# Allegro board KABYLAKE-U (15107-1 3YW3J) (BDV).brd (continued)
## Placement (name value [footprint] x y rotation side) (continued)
PR176  -  [0R0805-PAD]  137.07 198.5 180 bottom
PR177  2D2R5J-1-GP  [R805H24]  46.39 197.61 90 bottom
PR178  7K5R3F-2-GP  [R603H22]  19.34 197.21 90 bottom
PR179  2D2R3-1-U-GP  [R603H22]  32.29 196.85 270 bottom
PR180  909R2F-GP  [R402H16]  32.55 195.2 180 bottom
PR181  51KR2F-L-GP  [R402H16]  28.61 195.2 180 bottom
PR182  100R2F-L1-GP-U  [R402H14]  24.67 195.2 0 bottom
PR183  10R2F-L-GP  [R402H14]  23.66 195.2 0 bottom
PR184  0R0402-PAD-2-GP  [0R0402-PAD-1]  22.64 195.2 0 bottom
PR185  49D9R2F-GP  [R402H16]  21.62 195.2 0 bottom
PR186  -  [0R0402-PAD]  20.61 195.2 180 bottom
PR187  118KR2F-1-GP  [R402H16]  25.69 194.31 180 bottom
PR188  -  [0R0402-PAD]  19.59 194.18 180 bottom
PR189  12K7R2F-GP  [R402H16]  32.42 192.91 90 bottom
PR190  10KR2F-2-GP  [R402H16]  19.59 192.28 0 bottom
PR191  -  [0R0805-PAD]  45.25 192.15 0 bottom
PR192  -  [0R0805-PAD]  43.21 192.15 0 bottom
PR193  -  [0R0805-PAD]  41.18 192.15 0 bottom
PR194  -  [0R0805-PAD]  39.15 192.15 0 bottom
PR195  -  [0R0805-PAD]  37.12 192.15 0 bottom
PR196  -  [0R0805-PAD]  35.09 192.15 0 bottom
PR197  1K24R2F-GP  [R402H16]  29.47 191.97 90 bottom
PR198  -  [0R0805-PAD]  24.16 171.58 180 bottom
PR199  -  [0R0805-PAD]  22.13 171.58 180 bottom
PR200  -  [0R0805-PAD]  20.1 171.58 180 bottom
PR201  -  [0R0805-PAD]  27.72 168.78 270 bottom
PR202  2D2R5J-1-GP  [R805H24]  26.91 154.23 0 bottom
PR203  2D2R5J-1-GP  [R805H24]  36.74 149.73 90 bottom
PR204  53K6R2F-GP  [R402H16]  22.74 145.11 270 bottom
PR206  51R2F-2-GP  [R402H16]  122.84 105.92 0 bottom
PR207  10KR2F-2-GP  [R402H16]  120.81 105.92 180 bottom
PR208  2D2R5J-1-GP  [R805H24]  128.79 104.9 180 bottom
PR209  100KR2F-L1-GP  [R402H16]  133.51 104.14 0 bottom
PR210  -  [0R0402-PAD]  132.49 104.14 180 bottom
PR211  100KR2F-L1-GP  [R402H16]  127.29 104.14 0 bottom
PR212  -  [0R0402-PAD]  126.27 104.14 180 bottom
PR213  0R0402-PAD-2-GP  [0R0402-PAD-1]  120.81 103.89 0 bottom
PR214  82KR2F-1-GP  [R402H16]  124.72 103.5 270 bottom
PR215  100R2F-L1-GP-U  [R402H14]  122.33 103.5 90 bottom
PR216  2D2R5J-1-GP  [R805H24]  134.02 102.23 90 bottom
PR217  100R2F-L1-GP-U  [R402H14]  121.7 102.23 270 bottom
PR218  0R0402-PAD-2-GP  [0R0402-PAD-1]  121.7 101.22 270 bottom
PR219  47KR2F-GP  [R402H16]  121.7 100.2 90 bottom
PR220  35K7R2F-GP  [R402H16]  133.38 99.44 270 bottom
PR221  10KR2J-3-GP  [R402H16]  57.69 100.84 270 bottom
PR222  10KR2J-3-GP  [R402H16]  73.95 97.79 90 bottom
PR223  0R0402-PAD-1-GP  [0R0402-PAD]  120.56 96.77 0 bottom
PR224  20KR2F-L-GP  [R402H16]  119.54 96.77 180 bottom
PR225  2D2R5J-1-GP  [R805H24]  134.02 96.65 270 bottom
PR226  18KR2F-GP  [R402H16]  122.08 96.27 90 bottom
PR227  10KR2J-3-GP  [R402H16]  73.57 96.01 0 bottom
PR228  2KR2F-3-GP  [R402H16]  122.08 95.25 270 bottom
PR229  -  [0R0402-PAD]  131.73 94.61 0 bottom
PR230  47KR2J-2-GP  [R402H16]  130.72 94.61 0 bottom
PR231  1KR2J-1-GP  [R402H16]  127.8 94.61 180 bottom
PR232  33KR2F-GP  [R402H16]  126.78 94.61 0 bottom
PR233  0R0402-PAD-2-GP  [0R0402-PAD-1]  124.62 94.61 180 bottom
PR234  20KR2F-L-GP  [R402H16]  122.08 94.23 90 bottom
PR235  10KR2J-3-GP  [R402H16]  57.69 99.82 270 bottom
PR236  -  [0R0402-PAD]  120.94 78.61 90 bottom
PR237  -  [0R0402-PAD]  120.94 77.6 90 bottom
PR238  -  [0R0402-PAD]  120.94 76.58 90 bottom
PR239  470KR2J-2-GP  [R402H16]  37.88 73.53 90 bottom
PR240  0R0402-PAD-1-GP  [0R0402-PAD]  121.95 73.03 90 bottom
PR241  10KR2F-2-GP  [R402H16]  28.48 69.85 180 bottom
PR242  100KR2F-L1-GP  [R402H16]  24.67 69.85 180 bottom
PR243  0R2J-2-GP  [R402H16]  25.69 62.99 0 bottom
PR244  0R2J-2-GP  [R402H16]  24.67 62.99 0 bottom
PR245  680KR2F-GP  [R402H16]  25.18 61.47 90 bottom
PR246  20R5F-1GP  [R805H24]  46.9 50.16 90 bottom
PR247  1D5R2F-GP  [R402H16]  40.8 48.84 90 bottom
PR248  100KR2J-1-GP  [R402H16]  35.47 48.77 90 bottom
PR249  120KR2F-L-GP  [R402H16]  35.47 47.75 270 bottom
PR250  10R2F-L-GP  [R402H14]  37.75 45.34 90 bottom
PR251  10KR2F-2-GP  [R402H16]  54.8 45.06 180 bottom
PR252  3D3MR2J-GP  [R402H16]  48.01 44.7 180 bottom
PR253  7D5R2F-GP  [R402H16]  37.75 44.32 90 bottom
PR254  10KR2F-2-GP  [R402H16]  37.75 43.31 90 bottom
PR255  102KR2F-GP  [R402H16]  43.98 40.77 180 bottom
PR256  -  [0R0402-PAD]  42.96 40.77 180 bottom
PR257  0R5J-5-GP  [R805H24]  66.2 38.61 0 bottom
PR258  0R5J-5-GP  [R805H24]  64.17 38.61 0 bottom
PR259  0R5J-5-GP  [R805H24]  62.14 38.61 0 bottom
PR260  0R5J-5-GP  [R805H24]  68.23 37.97 0 bottom
PR261  -  [0R0805-PAD]  148.12 28.19 180 bottom
PR262  -  [0R0805-PAD]  146.08 28.19 180 bottom
PR263  100KR2F-L1-GP  [R402H16]  154.49 25.98 90 bottom
PR264  -  [0R0805-PAD]  130.59 26.04 180 bottom
PR265  -  [0R0805-PAD]  128.56 26.04 180 bottom
PR266  33KR2F-GP  [R402H16]  149.89 34.04 270 bottom
PR267  10KR2J-3-GP  [R402H16]  149.89 33.02 270 bottom
PR268  2D2R5J-1-GP  [R805H24]  138.21 15.62 0 bottom
PR270  2D2R5J-1-GP  [R805H24]  35.21 161.16 270 bottom
PR271  10KR2J-3-GP  [R402H16]  147.35 33.02 90 bottom
PR272  33KR2F-GP  [R402H16]  147.35 34.04 90 bottom
PR273  2D2R5J-1-GP  [R805H24]  24.98 154.23 0 bottom
PT1  SE47U25VM-13-GP  [SE361414H241]  88.3 216.28 0 top
PT2  SE47U25VM-13-GP  [SE361414H241]  37.88 208.41 0 top
PT3  SE330U2D5VM-16-GP  [CT7343H83]  94.9 207.14 0 top
PT4  SE330U2D5VM-16-GP  [CT7343H83]  100.11 207.14 0 top
PT5  SE47U25VM-13-GP  [SE361414H241]  37.88 198.5 180 top
PT6  E560U6D3VM-3-GP  [ECAP-100D6D3H375]  67.34 197.1 0 top
PT7  E560U6D3VM-3-GP  [ECAP-100D6D3H375]  59.85 190.25 90 top
PT8  E560U6D3VM-3-GP  [ECAP-100D6D3H375]  52.74 186.56 0 top
PT9  SE47U25VM-13-GP  [SE361414H241]  23.15 179.07 180 top
PT10  E560U6D3VM-3-GP  [ECAP-100D6D3H375]  52.87 178.69 90 top
PT11  E560U6D3VM-3-GP  [ECAP-100D6D3H375]  49.94 165.99 0 top
PT12  E820U2D5VM-6-GP  [ECAP-100D6D3H375]  55.66 154.31 0 top
PT13  SE47U25VM-13-GP  [SE361414H241]  33.31 147.96 180 top
PT14  E820U2D5VM-6-GP  [ECAP-100D6D3H375]  54.64 146.43 0 top
PT15  E820U2D5VM-6-GP  [ECAP-100D6D3H375]  106.21 92.84 0 top
PT16  E820U2D5VM-6-GP  [ECAP-100D6D3H375]  106.21 84.96 0 top
PT17  SE47U25VM-13-GP  [SE361414H241]  136.43 83.06 180 top
PT18  SE47U25VM-13-GP  [SE361414H241]  132.37 24.64 90 top
PT19  SE47U25VM-13-GP  [SE361414H241]  142.78 24.64 270 top
PT20  SE220U6D3VM-3GP  [SE3116H241]  135.03 7.87 90 top
PT21  SE220U6D3VM-3GP  [SE3116H241]  145.07 7.87 90 top
PU1  AON6520-GP  [PPAK-8P-5262H40]  44.99 215.26 90 top
PU2  AON6510-GP  [PPAK-8P-5262H40]  46.77 208.66 270 top
PU3  AON6510-GP  [PPAK-8P-5262H40]  46.77 202.06 270 top
PU4  AON6520-GP  [PPAK-8P-5262H40]  44.99 195.45 90 top
PU5  AON6510-GP  [PPAK-8P-5262H40]  32.16 182.5 270 top
PU6  AON6520-GP  [PPAK-8P-5262H40]  30.39 175.9 90 top
PU7  AON7410-GP  [PPAK-8P-3232H36]  33.43 166.12 90 top
PU8  NCP81253MNTBG-1-GP  [LFDFN8G2-G1309H40]  26.7 162.18 90 top
PU9  AON7506-GP  [PPAK-8P-3232H36]  34.96 161.67 270 top
PU10  APL5930KAI-TRG-1-GP  [SOIC8-G3530H63]  91.47 124.21 90 top
PU11  APL5912-KAC-TRG-GP  [SOIC8-G3530H63]  112.68 103.5 270 top
PU12  AON6510-GP  [PPAK-8P-5262H40]  127.68 89.03 90 top
PU13  AON6520-GP  [PPAK-8P-5262H40]  129.43 80.26 270 top
PU14  APW8713QBI-TRG-1-GP  [QFN23G4-G2P-1H42]  117.13 75.18 270 top
PU15  AO4407AL-GP  [SOIC8H69]  40.8 71.37 180 top
PU16  AO4407AL-GP  [SOIC8H69]  64.93 37.47 180 top
PU17  RT6575DGQW-GP  [QFN20-G1D75H32]  152.69 22.23 270 top
PU18  AON6520-GP  [PPAK-8P-5262H40]  93 222.5 180 bottom
PU19  AON6510-GP  [PPAK-8P-5262H40]  101.76 220.6 0 bottom
PU20  RT8231AGQW-GP  [QFN20-G1D75H32]  85.25 211.58 0 bottom
PU21  APL5930KAI-TRG-1-GP  [SOIC8-G3530H63]  134.02 204.98 270 bottom
PU22  AON6510-GP  [PPAK-8P-5262H40]  46.77 208.66 90 bottom
PU23  AON6510-GP  [PPAK-8P-5262H40]  46.77 202.06 90 bottom
PU24  NCP81206MNTXG-1-GP  [LFQFN52J6-G4D8-1H40]  25.94 201.55 180 bottom
PU25  AON6510-GP  [PPAK-8P-5262H40]  32.16 182.5 90 bottom
PU26  AON6520-GP  [PPAK-8P-5262H40]  30.39 175.9 270 bottom
PU27  AON6510-GP  [PPAK-8P-5262H40]  36.48 154.05 90 bottom
PU28  RT8237CZQW-2-GP  [DFN10G3-G265175H32]  23.66 149.1 270 bottom
PU29  AON6520-GP  [PPAK-8P-5262H40]  34.7 145.41 270 bottom
PU30  AON6510-GP  [PPAK-8P-5262H40]  127.68 89.03 270 bottom
PU31  AON6520-GP  [PPAK-8P-5262H40]  129.43 80.26 90 bottom
PU32  SIS412DN-T1-GE3-GP  [PPAK-8P-2H45]  43.21 54.99 0 bottom
PU33  SIS412DN-T1-GE3-GP  [PPAK-8P-2H45]  38.77 56.52 180 bottom
PU34  BQ24727RGRR-1-GP  [QFN20G3D5-G2D15H40]  42.32 45.21 90 bottom
PU35  AON7410-GP  [PPAK-8P-3232H36]  145.58 20.83 180 bottom
PU36  AON7410-GP  [PPAK-8P-3232H36]  131.1 20.83 180 bottom
PU37  AON7506-GP  [PPAK-8P-3232H36]  141.13 19.3 0 bottom
PU38  AON7506-GP  [PPAK-8P-3232H36]  135.54 19.3 0 bottom
PWRCN1  ACES-CON10-30-GP  [51530-01041-W01]  26.75 22.5 270 top
Q1  MMBT3904DW-GP  [SOT-363H44]  77.88 224.41 270 top
Q2  2N7002K-2-GP  [SOT23DGS2D4H44]  146.21 223.9 90 top
Q3  MMBT3904DW-GP  [SOT-363H44]  82.33 219.33 270 top
Q4  2N7002A-7-GP  [SOT23DGS2D4H48]  16.47 186.69 90 top
Q5  MMBT3904DW-GP  [SOT-363H44]  16.67 183.39 270 top
Q6  MMBT3904-4-GP  [SOT23CBE2D4H44]  161.96 182.63 90 top
Q7  2N7002A-7-GP  [SOT23DGS2D4H48]  16.67 179.96 90 top
Q8  MMBT3904DW-GP  [SOT-363H44]  16.67 176.53 270 top
Q9  2N7002KDW-1-GP  [SOT-363H44]  158.91 174.62 90 top
Q10  MMBT3904DW-GP  [SOT-363H44]  163.36 174.37 180 top
Q11  2N7002A-7-GP  [SOT23DGS2D4H48]  162.97 168.66 180 top
Q12  MMBT3904DW-GP  [SOT-363H44]  15.53 159.13 0 top
Q13  MMBT3904DW-GP  [SOT-363H44]  22.64 143.38 90 top
Q14  2N7002A-7-GP  [SOT23DGS2D4H48]  35.09 140.21 0 top
Q16  2N7002A-7-GP  [SOT23DGS2D4H48]  47.02 120.78 90 top
Q17  DMN5L06K-7-GP  [SOT23DGS2D4H48]  153.07 118.49 90 top
Q18  DMN5L06K-7-GP  [SOT23DGS2D4H48]  156.75 118.36 0 top
Q21  2N7002EDW-2-GP  [SOT-363H44]  76.23 116.2 270 top
Q22  MMBT3904-4-GP  [SOT23CBE2D4H44]  143.04 115.7 0 top
Q23  2N7002A-7-GP  [SOT23DGS2D4H48]  146.59 115.7 0 top
Q24  LMBT3904LT1G-GP  [SOT23CBE2D4H44]  168.31 111.63 90 top
Q25  2N7002-11-GP  [SOT23DGS2D4H44]  168.56 87.25 270 top
Q26  AZ5125-02S-R7G-GP  [SOT23-2D4-312H46]  174.02 85.47 0 top
Q27  AZ5125-02S-R7G-GP  [SOT23-2D4-312H46]  177.96 85.47 0 top
Q28  2N7002K-2-GP  [SOT23DGS2D4H44]  100.36 84.33 270 top
Q29  2N7002K-2-GP  [SOT23DGS2D4H44]  147.86 81.03 270 top
Q30  MMBT3904-4-GP  [SOT23CBE2D4H44]  151.67 79.76 0 top
Q31  2N7002A-7-GP  [SOT23DGS2D4H48]  55.41 79.5 90 top
Q32  AO3418L-GP  [SOT23DGS2D8H50]  64.04 78.74 180 top
Q33  MMBT3904DW-GP  [SOT-363H44]  54.26 75.56 90 top
Q34  2N7002KDW-GP  [SOT-363H44]  74.33 73.41 90 top
Q35  AO3413L-GP  [SOT23DGS2D8H50]  80.68 72.52 0 top
Q36  2N7002KDW-GP  [SOT-363H44]  147.23 67.56 270 top
Q37  2N7002A-7-GP  [SOT23DGS2D4H48]  82.33 66.67 180 top
Q38  2N7002A-7-GP  [SOT23DGS2D4H48]  164.12 65.28 270 top
Q39  2N7002KDW-GP  [SOT-363H44]  75.98 57.4 270 top
Q40  2N7002K-2-GP  [SOT23DGS2D4H44]  107.48 47.88 180 top
Q41  DMP2130L-7-GP  [SOT23DGS2D4H48]  145.07 44.96 0 top
Q42  AZ5125-02S-R7G-GP  [SOT23-2D4-312H46]  84.11 41.66 270 top
Q43  2N7002A-7-GP  [SOT23DGS2D4H48]  142.27 30.23 90 top
Q44  2N7002A-7-GP  [SOT23DGS2D4H48]  35.21 21.97 90 top
Q45  MMBT3904DW-GP  [SOT-363H44]  32.55 7.87 90 top
Q46  MMBT3904-4-GP  [SOT23CBE2D4H44]  42.96 6.99 0 top
Q47  MMBT3904-4-GP  [SOT23CBE2D4H44]  47.53 6.99 0 top
Q48  2N7002A-7-GP  [SOT23DGS2D4H48]  153.83 209.17 270 bottom
Q49  MMBT3904-4-GP  [SOT23CBE2D4H44]  150.02 209.17 90 bottom
Q50  AO3413L-GP  [SOT23DGS2D8H50]  146.46 201.68 0 bottom
Q51  2N7002A-7-GP  [SOT23DGS2D4H48]  56.8 122.17 90 bottom
Q52  MMBT3906-4-GP  [SOT23CBE2D4H44]  112.81 122.05 180 bottom
Q53  2N7002EDW-2-GP  [SOT-363H44]  76.23 116.2 270 bottom
Q54  2N7002A-7-GP  [SOT23DGS2D4H48]  92.74 110.49 180 bottom
Q55  AO3413L-GP  [SOT23DGS2D8H50]  41.69 100.08 0 bottom
Q56  2N7002A-7-GP  [SOT23DGS2D4H48]  38.01 99.95 180 bottom
Q57  2N7002A-7-GP  [SOT23DGS2D4H48]  157.01 78.11 270 bottom
Q58  MMBT3904DW-GP  [SOT-363H44]  54.26 75.56 90 bottom
Q59  MMBT3906-4-GP  [SOT23CBE2D4H44]  138.21 68.83 180 bottom
Q60  2N7002KDW-GP  [SOT-363H44]  85.76 64.9 270 bottom
Q61  AO3418L-GP  [SOT23DGS2D8H50]  61.25 62.23 180 bottom
Q62  LMBT3906LT1G-1-GP  [SOT23CBE2D4H44]  64.93 61.98 270 bottom
Q63  2N7002K-2-GP  [SOT23DGS2D4H44]  25.94 59.05 180 bottom
Q65  2N7002KDW-GP  [SOT-363H44]  75.98 57.4 270 bottom
Q66  2N7002A-7-GP  [SOT23DGS2D4H48]  160.56 51.56 270 bottom
Q67  2N7002K-2-GP  [SOT23DGS2D4H44]  145.32 48.77 180 bottom
Q68  2N7002A-7-GP  [SOT23DGS2D4H48]  163.99 45.72 90 bottom
Q69  2N7002A-7-GP  [SOT23DGS2D4H48]  141.77 44.83 0 bottom
Q70  2N7002A-7-GP  [SOT23DGS2D4H48]  145.32 43.56 0 bottom
Q71  MMBT3904DW-GP  [SOT-363H44]  155.86 41.91 90 bottom
Q72  2N7002KDW-GP  [SOT-363H44]  163.99 41.4 270 bottom
Q73  MMBT3904-4-GP  [SOT23CBE2D4H44]  50.45 36.45 180 bottom
Q74  2N7002A-7-GP  [SOT23DGS2D4H48]  55.02 36.32 0 bottom
Q75  AO4286-GP  [SOIC8H69]  39.28 35.31 270 bottom
Q76  MMBT3904-4-GP  [SOT23CBE2D4H44]  42.71 28.32 270 bottom
Q77  MMBT3904-4-GP  [SOT23CBE2D4H44]  25.94 27.18 0 bottom
Q78  MMBT3904DW-GP  [SOT-363H44]  24.8 21.84 0 bottom
Q79  2N7002A-7-GP  [SOT23DGS2D4H48]  25.18 12.83 180 bottom
Q80  MMBT3904-4-GP  [SOT23CBE2D4H44]  46.52 6.99 0 bottom
Q81  AO3413L-GP  [SOT23DGS2D8H50]  41.94 6.86 180 bottom
Q82  2N7002K-2-GP  [SOT23DGS2D4H44]  46.26 19.68 0 top
Q83  2N7002A-7-GP  [SOT23DGS2D4H48]  112.68 102.62 90 bottom
Q84  2N7002A-7-GP  [SOT23DGS2D4H48]  154.59 47.75 180 bottom
R1  51R2J-2-GP  [R402H16]  15.53 224.66 0 top
R2  1KR2J-1-GP  [R402H16]  16.67 224.66 0 top
R3  1KR2J-1-GP  [R402H16]  17.81 224.66 0 top
R4  -  [0R0402-PAD]  18.83 224.66 180 top
R5  1K5R2J-3-GP  [R402H16]  47.84 224.54 270 top
R6  10KR2J-3-GP  [R402H16]  143.54 224.54 180 top
R7  -  [0R0402-PAD]  28.99 224.16 180 top
R8  -  [0R0402-PAD]  30.01 224.16 180 top
R9  1KR2J-1-GP  [R402H16]  32.93 224.16 0 top
R10  -  [0R0402-PAD]  33.94 224.16 0 top
R11  -  [0R0402-PAD]  34.96 224.16 0 top
R12  -  [0R0402-PAD]  35.97 224.16 180 top
R13  51R2J-2-GP  [R402H16]  36.99 224.16 180 top
R14  -  [0R0402-PAD]  38.01 224.16 0 top
R15  -  [0R0402-PAD]  39.02 224.16 0 top
R16  0R2J-2-GP  [R402H16]  40.04 224.16 180 top
R17  100KR2J-1-GP  [R402H16]  41.05 224.16 0 top
R18  -  [0R0402-PAD]  42.07 224.16 0 top
R19  150R2J-L1-GP-U  [R402H16]  43.21 224.16 0 top
R20  1KR2J-1-GP  [R402H16]  44.36 224.16 0 top
R21  0R2J-2-GP  [R402H16]  49.56 224.16 180 top
R22  -  [0R0402-PAD]  50.58 224.16 0 top
R23  -  [0R0402-PAD]  46.39 224.03 180 top
R24  10KR2J-3-GP  [R402H16]  122.08 223.77 180 top
R25  100KR2J-1-GP  [R402H16]  123.1 223.77 180 top
R26  0R2J-2-GP  [R402H16]  52.36 223.65 90 top
R27  0R2J-2-GP  [R402H16]  47.84 223.52 270 top
R28  -  [0R0402-PAD]  52.36 222.63 270 top
R29  10KR2J-3-GP  [R402H16]  79.41 222.38 90 top
R30  0R0402-PAD-2-GP  [0R0402-PAD-1]  123.99 222 90 top
R31  -  [0R0402-PAD]  105.82 221.87 180 top
R32  -  [0R0402-PAD]  52.36 221.49 90 top
R33  2K2R2J-2-GP  [R402H16]  12.23 220.98 0 top
R34  0R0402-PAD-2-GP  [0R0402-PAD-1]  123.99 220.98 270 top
R35  -  [0R0402-PAD]  52.36 220.34 90 top
R36  0R2J-2-GP  [R402H16]  125.89 220.34 270 top
R37  0R2J-2-GP  [R402H16]  104.58 219.84 180 top
R38  10KR2J-3-GP  [R402H16]  75.09 219.71 180 top
R39  0R2J-2-GP  [R402H16]  123.99 219.71 270 top
R40  100R2F-L1-GP-U  [R402H14]  11.84 219.46 90 top
R41  0R2J-2-GP  [R402H16]  125.89 219.07 270 top
R42  10KR2J-3-GP  [R402H16]  79.15 218.82 180 top
R43  -  [0R0402-PAD]  106.84 218.44 90 top
R44  0R2J-2-GP  [R402H16]  123.99 218.44 270 top
R45  0R2J-2-GP  [R402H16]  125.89 217.81 270 top
R46  0R0402-PAD-2-GP  [0R0402-PAD-1]  106.46 217.42 270 top
R47  0R2J-2-GP  [R402H16]  79.54 217.3 90 top
R48  0R2J-2-GP  [R402H16]  81.44 215.77 270 top
R49  0R2J-2-GP  [R402H16]  123.99 217.42 270 top
R50  0R0402-PAD-2-GP  [0R0402-PAD-1]  106.46 216.41 270 top
R51  0R2J-2-GP  [R402H16]  79.54 216.28 90 top
R52  0R2J-2-GP  [R402H16]  123.99 216.41 270 top
R53  0R0402-PAD-2-GP  [0R0402-PAD-1]  106.46 214.76 270 top
R54  0R0402-PAD-2-GP  [0R0402-PAD-1]  106.46 213.74 270 top
R55  0R0402-PAD-2-GP  [0R0402-PAD-1]  105.57 208.2 0 top
R56  0R0402-PAD-2-GP  [0R0402-PAD-1]  106.59 208.2 0 top
R57  4K7R2J-2-GP  [R402H16]  17.18 211.46 0 top
R58  1KR2J-1-GP  [R402H16]  19.16 210.69 270 top
R59  8K2R2F-1-GP  [R402H16]  17.18 209.55 180 top
R60  0R0402-PAD-2-GP  [0R0402-PAD-1]  18.7 209.17 0 top
R61  20KR2J-L2-GP  [R402H16]  17.18 207.65 180 top
R62  -  [0R0402-PAD]  163.99 206.5 0 top
R63  -  [0R0402-PAD]  113.95 201.04 90 top
R64  0R2J-2-GP  [R402H16]  116.14 200.38 90 top
R65  1KR2J-1-GP  [R402H16]  70.26 192.15 90 top
R66  -  [0R0402-PAD]  100.87 192.02 0 top
R67  -  [0R0805-PAD]  15.65 191.39 180 top
R68  -  [0R0805-PAD]  17.69 191.39 180 top
R69  100R2F-L1-GP-U  [R402H14]  76.87 190.5 0 top
R70  60D4R2F-GP  [R402H16]  69.5 189.87 0 top
R71  10KR2J-3-GP  [R402H16]  71.79 189.87 180 top
R72  1KR2J-1-GP  [R402H16]  70.77 189.1 180 top
R73  1KR2J-1-GP  [R402H16]  72.8 189.1 180 top
R74  1KR2J-1-GP  [R402H16]  73.82 189.1 180 top
R75  100R2F-L1-GP-U  [R402H14]  77.76 188.98 90 top
R76  1KR2J-1-GP  [R402H16]  19.85 188.8 90 top
R77  10KR2J-3-GP  [R402H16]  22 188.09 90 top
R78  10KR2J-3-GP  [R402H16]  23.66 188.09 0 top
R79  0R3J-0-U-GP  [R603H22]  160.18 188.09 90 top
R80  -  [0R0402-PAD]  19.85 187.78 270 top
R81  1KR2J-1-GP  [R402H16]  67.39 187.58 180 top
R82  499R2F-2-GP  [R402H16]  68.41 187.58 0 top
R83  100KR2J-1-GP  [R402H16]  64.68 187.32 180 top
R84  0R3J-0-U-GP  [R603H22]  164.5 186.94 180 top
R85  10KR2J-3-GP  [R402H16]  20.48 186.18 270 top
R86  54D9R2F-L1-GP  [R402H16]  64.68 185.42 0 top
R87  100R2F-L1-GP-U  [R402H14]  67.42 184.66 0 top
R88  0R0402-PAD-2-GP  [0R0402-PAD-1]  68.44 184.66 180 top
R89  0R0402-PAD-2-GP  [0R0402-PAD-1]  65.69 184.53 0 top
R90  10KR2J-3-GP  [R402H16]  12.35 184.15 0 top
R91  10KR2J-3-GP  [R402H16]  13.37 184.15 0 top
R92  56R2J-4-GP  [R402H16]  67.42 182.63 180 top
R93  220R2J-L2-GP  [R402H16]  68.44 182.63 180 top
R94  1KR2J-1-GP  [R402H16]  65.36 181.64 0 top
R95  10KR2J-3-GP  [R402H16]  12.35 181.23 180 top
R96  -  [0R0402-PAD]  67.98 181.1 90 top
R97  10KR2J-3-GP  [R402H16]  161.04 186.23 180 top
R98  1KR2J-1-GP  [R402H16]  158.66 180.59 90 top
R99  51R2J-2-GP  [R402H16]  67.98 179.96 270 top
R100  51R2J-2-GP  [R402H16]  65.69 179.71 180 top
R101  -  [0R0402-PAD]  158.66 179.45 270 top
R102  1KR2J-1-GP  [R402H16]  13.5 179.2 0 top
R103  51R2J-2-GP  [R402H16]  67.85 178.56 270 top
R104  10KR2J-3-GP  [R402H16]  158.66 178.44 90 top
R105  51R2J-2-GP  [R402H16]  65.69 177.8 180 top
R106  10KR2J-3-GP  [R402H16]  161.2 177.24 270 top
R107  1KR2J-1-GP  [R402H16]  67.85 176.91 270 top
R108  10KR2J-3-GP  [R402H16]  12.45 176.68 0 top
R109  10KR2J-3-GP  [R402H16]  161.32 175.13 180 top
R110  51R2J-2-GP  [R402H16]  66.33 175.77 270 top
R111  51R2J-2-GP  [R402H16]  66.33 174.5 270 top
R112  NTC-100K-8-GP  [NTC-603H38]  40.17 174.12 90 top
R113  51R2J-2-GP  [R402H16]  63.53 173.99 180 top
R114  51R2J-2-GP  [R402H16]  64.68 173.99 180 top
R115  -  [0R0402-PAD]  64.17 171.96 270 top
R116  10KR2J-3-GP  [R402H16]  165.84 171.96 90 top
R117  10R6J-1-GP  [R1206H28]  159.42 171.7 90 top
R118  10KR2J-3-GP  [R402H16]  159.8 169.93 270 top
R119  NTC-100K-8-GP  [NTC-603H38]  102.9 169.67 180 top
R120  10KR2J-3-GP  [R402H16]  159.42 168.15 180 top
R121  10KR2J-3-GP  [R402H16]  165.39 167.77 180 top
R122  150KR2J-GP  [R402H16]  102.52 163.96 270 top
R123  33R2J-2-GP  [R402H16]  102.52 162.94 270 top
R124  33R2J-2-GP  [R402H16]  102.52 161.93 270 top
R125  -  [0R0402-PAD]  15.02 161.54 270 top
R126  33R2J-2-GP  [R402H16]  102.52 160.91 270 top
R127  33R2J-2-GP  [R402H16]  102.52 159.89 270 top
R128  1MR2J-1-GP  [R402H16]  65.82 159.84 90 top
R129  10KR2F-2-GP  [R402H16]  18.07 159.38 90 top
R130  0R2J-2-GP  [R402H16]  102.52 158.5 270 top
R131  10KR2F-2-GP  [R402H16]  18.07 158.37 90 top
R132  1K8R2F-GP  [R402H16]  15.15 156.21 270 top
R133  5K6R2F-2-GP  [R402H16]  15.15 155.19 90 top
R134  33R2J-2-GP  [R402H16]  102.06 154.25 90 top
R135  1KR2J-1-GP  [R402H16]  102.52 152.53 270 top
R136  -  [0R0402-PAD]  100.36 152.15 90 top
R137  0R0603-PAD-2-GP-U  [0R0603-PAD-1-U]  102.9 150.62 180 top
R138  -  [0R0402-PAD]  59.6 147.19 90 top
R139  -  [0R0402-PAD]  59.6 146.18 90 top
R140  -  [0R0402-PAD]  59.6 145.16 90 top
R141  -  [0R0402-PAD]  59.6 144.15 90 top
R142  -  [0R0402-PAD]  59.6 143.13 90 top
R144  -  [0R0402-PAD]  59.6 142.11 90 top
R146  -  [0R0402-PAD]  52.87 141.73 0 top
R147  10KR2J-3-GP  [R402H16]  68.11 141.73 0 top
R148  -  [0R0402-PAD]  42.07 141.48 0 top
R149  -  [0R0402-PAD]  44.23 141.48 0 top
R150  -  [0R0402-PAD]  46.26 141.48 0 top
R151  3KR2J-2-GP  [R402H16]  70.01 141.43 270 top
R152  10KR2J-3-GP  [R402H16]  75.85 141.48 270 top
R153  -  [0R0402-PAD]  102.9 140.08 180 top
R156  -  [0R0805-PAD]  54.39 140.72 0 top
R157  10KR2J-3-GP  [R402H16]  21.24 140.59 0 top
R158  10KR2J-3-GP  [R402H16]  22.28 140.59 180 top
R159  10KR2J-3-GP  [R402H16]  23.3 140.59 180 top
R160  1KR2J-1-GP  [R402H16]  88.43 140.59 90 top
R161  -  [0R0402-PAD]  70.01 140.41 90 top
R162  49K9R2F-L-GP  [R402H16]  86.01 139.95 90 top
R163  -  [0R0402-PAD]  66.33 135.25 270 top
R164  49K9R2F-L-GP  [R402H16]  86.01 138.94 90 top
R165  10KR2J-3-GP  [R402H16]  71.92 138.43 90 top
R166  10KR2J-3-GP  [R402H16]  100.36 138.68 0 top
R167  10KR2J-3-GP  [R402H16]  74.71 138.76 270 top
R168  200R2F-L-GP  [R402H16]  86.01 137.79 270 top
R169  -  [0R0402-PAD]  50.83 137.92 180 top
R170  -  [0R0402-PAD]  51.85 137.92 180 top
R171  10KR2J-3-GP  [R402H16]  34.7 137.79 90 top
R172  10KR2J-3-GP  [R402H16]  72.3 137.29 90 top
R173  1KR2J-1-GP  [R402H16]  86.01 136.78 90 top
R174  22R2J-2-GP  [R402H16]  103.03 136.78 180 top
R175  -  [0R0402-PAD]  78.52 136.65 180 top
R176  15R2J-GP  [R402H16]  85.25 135.76 90 top
R177  0R2J-2-GP  [R402H16]  81.57 135.25 180 top
R178  -  [0R0402-PAD]  82.58 135.25 180 top
R179  -  [0R0402-PAD]  83.6 135.25 0 top
R180  -  [0R0402-PAD]  76.87 135.13 90 top
R181  -  [0R0402-PAD]  78.77 135.13 90 top
R182  -  [0R0402-PAD]  84.74 134.24 0 top
R183  15R2J-GP  [R402H16]  85.76 134.24 180 top
R184  -  [0R0402-PAD]  78.77 134.11 90 top
R185  1KR2J-1-GP  [R402H16]  87.28 133.86 270 top
R186  22R2J-2-GP  [R402H16]  103.03 133.6 180 top
R187  10KR2J-3-GP  [R402H16]  64.52 132.46 0 top
R188  10KR2J-3-GP  [R402H16]  65.54 131.88 180 top
R189  10KR2J-3-GP  [R402H16]  66.56 131.88 180 top
R190  10KR2J-3-GP  [R402H16]  67.6 133.48 0 top
R191  10KR2J-3-GP  [R402H16]  68.61 133.48 0 top
R192  10KR2J-3-GP  [R402H16]  70.26 133.48 180 top
R193  -  [0R0402-PAD]  100.62 132.08 180 top
R194  15R2J-GP  [R402H16]  85.25 131.95 180 top
R195  1KR2J-1-GP  [R402H16]  86.27 131.95 180 top
R196  15R2J-GP  [R402H16]  87.28 131.95 180 top
R197  15R2J-GP  [R402H16]  88.3 131.95 180 top
R198  10MR2J-L-GP  [R402H16]  89.57 131.95 180 top
R199  1KR2J-1-GP  [R402H16]  83.73 131.32 90 top
R200  1KR2J-1-GP  [R402H16]  83.73 130.3 90 top
R201  -  [0R0402-PAD]  77.38 129.67 270 top
R202  0R2J-2-GP  [R402H16]  101.63 129.54 180 top
R203  -  [0R0402-PAD]  96.27 128.73 0 top
R204  -  [0R0402-PAD]  97.29 128.73 0 top
R205  -  [0R0402-PAD]  77.38 128.65 270 top
R206  10KR2J-3-GP  [R402H16]  100.62 128.65 180 top
R207  -  [0R0402-PAD]  93.23 128.55 180 top
R208  0R2J-2-GP  [R402H16]  94.24 128.55 180 top
R209  0R2J-2-GP  [R402H16]  95.26 128.55 180 top
R210  -  [0R0402-PAD]  91.6 128.52 180 top
R213  1KR2J-1-GP  [R402H16]  100.62 126.24 0 top
R214  0R2J-2-GP  [R402H16]  161.45 125.86 270 top
R215  -  [0R0402-PAD]  159.55 124.84 90 top
R216  10KR2J-3-GP  [R402H16]  108.49 124.08 0 top
R217  0R0402-PAD-2-GP  [0R0402-PAD-1]  109.51 124.08 180 top
R220  -  [0R0402-PAD]  86.65 122.05 90 top
R223  10KR2J-3-GP  [R402H16]  44.61 120.78 180 top
R224  1KR2J-1-GP  [R402H16]  152.94 120.78 270 top
R225  1KR2J-1-GP  [R402H16]  155.99 120.78 90 top
R226  10KR2J-3-GP  [R402H16]  106.46 120.65 270 top
R228  1KR2J-1-GP  [R402H16]  159.04 118.87 180 top
R229  10KR2J-3-GP  [R402H16]  160.69 118.87 180 top
R230  0R3J-0-U-GP  [R603H22]  115.6 118.36 0 top
R231  15KR2F-GP  [R402H16]  162.21 118.36 90 top
R233  8K2R2J-3-GP  [R402H16]  150.15 117.47 90 top
R235  10KR2J-3-GP  [R402H16]  73.19 116.97 90 top
R237  10KR3J-L1-GP  [R603H22]  79.36 116.46 270 top
R238  10KR3J-L1-GP  [R603H22]  73.06 115.82 90 top
R240  10KR2J-3-GP  [R402H16]  93.25 114.55 0 top
R241  10KR2J-3-GP  [R402H16]  81.69 114.05 270 top
R242  10KR2J-3-GP  [R402H16]  94.27 114.55 0 top
R243  2K49R2F-GP  [R402H16]  72.91 114.6 270 top
R244  200R2F-L-GP  [R402H16]  77.25 114.07 90 top
R245  0R2J-2-GP  [R402H16]  97.7 113.92 90 top
R246  10KR2J-3-GP  [R402H16]  97.7 112.9 270 top
R247  0R2J-2-GP  [R402H16]  97.7 111.89 270 top
R248  8K2R2J-3-GP  [R402H16]  147.02 111.84 270 top
R249  931R2F-1-GP  [R402H16]  47.28 111.63 270 top
R250  NTC-100K-8-GP  [NTC-603H38]  165.77 111.63 180 top
R251  -  [0R0402-PAD]  97.7 110.87 270 top
R252  10KR2J-3-GP  [R402H16]  125.38 112.01 270 bottom
R253  1KR2F-3-GP  [R402H16]  47.79 108.2 0 top
R254  4K7R2J-2-GP  [R402H16]  108.62 111.12 180 top
R255  10KR2J-3-GP  [R402H16]  45.75 105.79 180 top
R256  -  [0R0402-PAD]  160.94 105.54 270 top
R257  -  [0R0402-PAD]  160.94 104.52 270 top
R258  1KR2F-3-GP  [R402H16]  45.75 103.89 180 top
R259  100R2F-L1-GP-U  [R402H14]  45.75 101.98 180 top
R260  40K2R2F-GP  [R402H16]  97.44 100.33 270 top
R261  1KR2J-1-GP  [R402H16]  137.32 99.82 180 top
R262  10KR2F-2-GP  [R402H16]  97.44 99.31 270 top
R263  10KR2F-2-GP  [R402H16]  97.44 98.3 90 top
R264  0R2J-2-GP  [R402H16]  97.44 97.28 90 top
R265  -  [0R0402-PAD]  136.69 96.14 90 top
R266  10KR2F-2-GP  [R402H16]  98.84 95.25 90 top
R267  10KR2F-2-GP  [R402H16]  97.44 94.23 270 top
R268  0R2J-2-GP  [R402H16]  136.69 94.11 90 top
R269  49K9R2F-L-GP  [R402H16]  99.98 90.17 90 top
R270  10KR2F-2-GP  [R402H16]  99.98 91.19 270 top
R271  10KR2F-2-GP  [R402H16]  97.44 91.31 90 top
R273  0R0603-PAD-2-GP-U  [0R0603-PAD-1-U]  164.88 90.93 180 top
R274  10KR2F-2-GP  [R402H16]  98.08 89.28 270 top
R275  10KR2F-2-GP  [R402H16]  97.44 88.27 270 top
R276  10KR2F-2-GP  [R402H16]  98.08 87.25 90 top
R277  0R0603-PAD-2-GP-U  [0R0603-PAD-1-U]  160.05 87.63 0 top
R278  0R0603-PAD-2-GP-U  [0R0603-PAD-1-U]  166.05 88.14 0 top
R279  1KR2J-1-GP  [R402H16]  101.38 87.5 0 top
R280  2K2R2J-2-GP  [R402H16]  171.1 84.96 90 top
R281  1KR2J-1-GP  [R402H16]  171.1 83.95 90 top
R282  47KR2F-GP  [R402H16]  154.85 83.69 0 top
R283  10KR2F-2-GP  [R402H16]  89.57 83.57 0 top
R284  10KR2F-2-GP  [R402H16]  90.58 83.57 0 top
R285  10KR2F-2-GP  [R402H16]  91.6 83.57 180 top
R286  2K2R2J-2-GP  [R402H16]  92.62 83.57 180 top
R287  2K2R2J-2-GP  [R402H16]  93.63 83.57 180 top
R288  100KR2J-1-GP  [R402H16]  94.65 83.57 0 top
R289  100KR2J-1-GP  [R402H16]  95.66 83.57 0 top
R290  100KR2J-1-GP  [R402H16]  96.68 83.57 0 top
R291  0R2J-2-GP  [R402H16]  146.97 83.57 270 top
R292  0R2J-2-GP  [R402H16]  148.88 83.57 90 top
R293  1MR3F-GP  [R603H22]  150.66 83.06 180 top
R294  10R2F-L-GP  [R402H14]  171.1 82.93 90 top
R295  549R2F-GP  [R402H16]  52.74 82.8 90 top
R296  100KR2F-L1-GP  [R402H16]  151.8 82.68 0 top
R297  10KR2J-3-GP  [R402H16]  173.64 82.42 0 top
R298  931R2F-1-GP  [R402H16]  54.26 82.3 0 top
R299  1K33R2F-GP  [R402H16]  55.28 82.3 0 top
R300  121R2F-GP  [R402H16]  57.31 82.3 0 top
R301  121R2F-GP  [R402H16]  58.33 82.3 0 top
R302  40D2R2F-GP  [R402H16]  59.47 82.3 0 top
R303  40D2R2F-GP  [R402H16]  60.49 82.3 0 top
R304  0R3J-0-U-GP  [R603H22]  179.61 82.04 270 top
R305  0R0402-PAD-2-GP  [0R0402-PAD-1]  155.74 81.66 0 top
R306  47KR2F-GP  [R402H16]  156.75 81.66 180 top
R307  0R0603-PAD-2-GP-U  [0R0603-PAD-1-U]  158.78 81.15 90 top
R308  10KR2F-2-GP  [R402H16]  77.15 80.16 180 top
R309  10KR2F-2-GP  [R402H16]  78.16 80.16 180 top
R310  24K9R2F-L-GP  [R402H16]  79.18 80.16 0 top
R311  33R2J-2-GP  [R402H16]  80.2 80.16 0 top
R312  10KR2J-3-GP  [R402H16]  155.86 79.76 0 top
R313  20KR2F-L-GP  [R402H16]  167.34 78.99 0 top
R314  0R2J-2-GP  [R402H16]  146.97 78.74 270 top
R315  2KR2F-3-GP  [R402H16]  148.88 78.74 270 top
R316  10KR2J-3-GP  [R402H16]  60.74 78.36 180 top
R317  -  [0R0402-PAD]  61.76 78.36 180 top
R318  4K99R2F-L-GP  [R402H16]  79.54 78.23 180 top
R319  33R2J-2-GP  [R402H16]  80.55 78.23 180 top
R320  0R2J-2-GP  [R402H16]  156.24 78.11 270 top
R321  10KR2J-3-GP  [R402H16]  67.6 77.72 180 top
R322  10KR2F-2-GP  [R402H16]  81.69 77.6 180 top
R323  2K2R2J-2-GP  [R402H16]  169.96 77.47 0 top
R324  10KR2J-3-GP  [R402H16]  57.06 76.58 270 top
R325  10KR2J-3-GP  [R402H16]  71.92 76.2 90 top
R326  10KR2J-3-GP  [R402H16]  73.82 76.2 90 top
R327  33R2J-2-GP  [R402H16]  156.24 76.07 90 top
R328  0R2J-2-GP  [R402H16]  62.69 75.77 180 top
R329  4K7R2J-2-GP  [R402H16]  67.6 75.64 180 top
R330  10KR2J-3-GP  [R402H16]  68.74 75.64 0 top
R331  10KR2J-3-GP  [R402H16]  69.76 75.64 0 top
R332  10KR2J-3-GP  [R402H16]  57.06 75.56 270 top
R333  2K2R2J-2-GP  [R402H16]  169.96 75.31 180 top
R334  10KR2F-2-GP  [R402H16]  84.49 75.06 90 top
R335  33R2J-2-GP  [R402H16]  86.52 75.06 270 top
R336  4K99R2F-L-GP  [R402H16]  88.43 75.06 90 top
R337  1KR2J-1-GP  [R402H16]  152.43 75.06 270 top
R338  2K2R2J-2-GP  [R402H16]  168.44 74.55 90 top
R339  -  [0R0402-PAD]  77.88 74.42 270 top
R340  10R2F-L-GP  [R402H14]  168.44 73.53 90 top
R341  10KR2J-3-GP  [R402H16]  169.96 73.41 0 top
R342  10KR2J-3-GP  [R402H16]  78.27 72.9 180 top
R343  0R5J-5-GP  [R805H24]  83.47 72.64 0 top
R344  1KR2J-1-GP  [R402H16]  168.44 72.52 90 top
R345  10KR2F-2-GP  [R402H16]  169.96 71.5 180 top
R346  5K1R2F-2-GP  [R402H16]  170.98 71.5 180 top
R347  -  [0R0402-PAD]  72.8 70.23 90 top
R348  -  [0R0402-PAD]  159.16 70.05 180 top
R349  68R2F-GP  [R402H16]  156.75 69.93 270 top
R350  0R2J-2-GP  [R402H16]  121.95 69.85 270 top
R353  8K2R2J-3-GP  [R402H16]  81.57 69.6 180 top
R354  100KR2J-1-GP  [R402H16]  82.58 69.6 0 top
R355  18K7R2F-GP  [R402H16]  151.93 69.6 270 top
R356  100KR2J-1-GP  [R402H16]  72.8 69.22 270 top
R357  39K2R2F-L-GP  [R402H16]  79.92 69.09 270 top
R358  100KR2J-1-GP  [R402H16]  137.7 68.83 0 top
R359  -  [0R0402-PAD]  140.5 68.45 0 top
R360  0R2J-2-GP  [R402H16]  132.52 69.04 180 top
R361  -  [0R0402-PAD]  139.48 68.45 180 top
R362  -  [0R0402-PAD]  131.22 68.45 0 top
R363  1KR2J-1-GP  [R402H16]  72.8 68.2 90 top
R364  1KR2J-1-GP  [R402H16]  142.78 67.82 90 top
R365  0R2J-2-GP  [R402H16]  128.81 66.67 90 top
R366  0R0603-PAD-2-GP-U  [0R0603-PAD-1-U]  160.69 65.53 90 top
R367  -  [0R0402-PAD]  126.78 64.9 90 top
R368  15KR2F-GP  [R402H16]  126.78 62.87 270 top
R369  0R0603-PAD-2-GP-U  [0R0603-PAD-1-U]  163.36 62.87 270 top
R370  0R2J-2-GP  [R402H16]  35.09 62.99 180 top
R371  24K9R2F-L-GP  [R402H16]  121.95 62.74 90 top
R372  24K9R2F-L-GP  [R402H16]  123.48 62.66 180 top
R373  0R0603-PAD-2-GP-U  [0R0603-PAD-1-U]  153.83 62.2 90 top
R374  0R2J-2-GP  [R402H16]  36.1 61.98 0 top
R375  0R0603-PAD-2-GP-U  [0R0603-PAD-1-U]  163.36 61.7 90 top
R376  10KR2F-2-GP  [R402H16]  165.39 61.47 0 top
R377  0R0603-PAD-2-GP-U  [0R0603-PAD-1-U]  153.83 61.04 270 top
R378  0R2J-2-GP  [R402H16]  148.37 60.96 90 top
R379  10KR2J-3-GP  [R402H16]  112.17 61.21 270 top
R380  -  [0R0402-PAD]  107.98 61.21 90 top
R381  4K7R2J-2-GP  [R402H16]  110.4 60.07 270 top
R382  24K9R2F-L-GP  [R402H16]  123.48 60.76 0 top
R383  24K9R2F-L-GP  [R402H16]  121.95 60.2 90 top
R385  10K5R3F-GP  [R603H22]  155.35 59.82 90 top
R386  10K5R3F-GP  [R603H22]  163.36 59.77 270 top
R387  100KR2J-1-GP  [R402H16]  159.16 59.69 180 top
R388  -  [0R0402-PAD]  158.15 59.66 180 top
R389  -  [0R0402-PAD]  152.1 57.61 270 top
R390  0R2J-2-GP  [R402H16]  124.49 58.57 90 top
R391  0R0603-PAD-2-GP-U  [0R0603-PAD-1-U]  155.35 58.55 270 top
R392  0R0603-PAD-2-GP-U  [0R0603-PAD-1-U]  163.36 58.55 90 top
R393  10KR2J-3-GP  [R402H16]  73.44 53.59 0 top
R394  0R2J-2-GP  [R402H16]  124.49 57.56 90 top
R395  0R0603-PAD-2-GP-U  [0R0603-PAD-1-U]  164.5 57.35 90 top
R396  0R0603-PAD-2-GP-U  [0R0603-PAD-1-U]  158.76 57.25 270 top
R397  -  [0R0402-PAD]  126.02 57.02 0 top
R398  10KR2J-3-GP  [R402H16]  148.37 56.64 90 top
R399  -  [0R0402-PAD]  46.64 56.13 270 top
R400  10KR2J-3-GP  [R402H16]  74.46 53.59 180 top
R401  0R0402-PAD-2-GP  [0R0402-PAD-1]  155.48 55.63 90 top
R402  0R2J-2-GP  [R402H16]  46.64 55.12 270 top
R403  12KR2F-L-GP  [R402H16]  66.58 54.74 90 top
R404  0R2J-2-GP  [R402H16]  124.75 54.74 90 top
R405  100KR2J-1-GP  [R402H16]  161.07 54.61 270 top
R406  3K9R2F-GP  [R402H16]  163.66 54.61 0 top
R407  5K6R2F-2-GP  [R402H16]  159.6 54.58 0 top
R408  10KR2F-2-GP  [R402H16]  162.57 54.23 0 top
R409  47R2J-2-GP  [R402H16]  76.49 54.1 90 top
R410  -  [0R0402-PAD]  124.75 53.72 90 top
R411  47R2J-2-GP  [R402H16]  76.49 53.09 90 top
R412  0R0402-PAD-2-GP  [0R0402-PAD-1]  124.75 52.7 270 top
R413  56R2J-4-GP  [R402H16]  55.15 52.32 180 top
R414  22R2J-2-GP  [R402H16]  56.17 52.32 180 top
R415  22R2J-2-GP  [R402H16]  57.18 52.32 0 top
R416  22R2J-2-GP  [R402H16]  58.2 52.32 0 top
R417  -  [0R0402-PAD]  59.22 52.32 0 top
R418  -  [0R0402-PAD]  60.23 52.32 0 top
R419  -  [0R0402-PAD]  61.25 52.32 0 top
R420  -  [0R0402-PAD]  62.26 52.32 0 top
R421  -  [0R0402-PAD]  63.28 52.32 0 top
R422  -  [0R0402-PAD]  64.3 52.32 0 top
R423  1MR2J-1-GP  [R402H16]  66.07 52.2 180 top
R424  1MR2J-1-GP  [R402H16]  74.84 51.56 180 top
R425  100KR2J-1-GP  [R402H16]  75.85 51.56 0 top
R426  1KR2J-1-GP  [R402H16]  106.71 51.31 90 top
R427  0R0402-PAD-2-GP  [0R0402-PAD-1]  152.69 51.31 90 top
R428  0R2J-2-GP  [R402H16]  125.38 51.18 0 top
R429  0R0402-PAD-2-GP  [0R0402-PAD-1]  122.72 50.93 90 top
R430  10MR2J-L-GP  [R402H16]  106.71 50.29 270 top
R431  10R3J-3-GP  [R603H22]  152.31 50.16 90 top
R432  100KR2J-1-GP  [R402H16]  74.84 49.66 0 top
R433  1MR2J-1-GP  [R402H16]  75.85 49.66 180 top
R434  10KR2J-3-GP  [R402H16]  122.72 48.9 270 top
R436  -  [0R0402-PAD]  125.36 45.75 270 top
R438  43R2J-GP  [R402H16]  137.07 45.47 0 top
R439  0R2J-2-GP  [R402H16]  138.46 45.47 0 top
R440  -  [0R0402-PAD]  139.48 45.47 0 top
R441  10KR2J-3-GP  [R402H16]  141 45.09 270 top
R442  0R2J-2-GP  [R402H16]  125.48 44.7 90 top
R443  0R2J-2-GP  [R402H16]  128.43 44.58 180 top
R444  -  [0R0402-PAD]  134.15 45.47 180 top
R445  -  [0R0402-PAD]  132.62 44.2 270 top
R446  -  [0R0402-PAD]  32.67 42.55 0 top
R447  100KR2J-1-GP  [R402H16]  137.19 52.2 270 bottom
R448  20KR2F-L-GP  [R402H16]  148.24 42.04 180 top
R449  1KR2J-1-GP  [R402H16]  147.99 46.23 0 top
R450  330KR2J-L1-GP  [R402H16]  146.72 41.53 270 top
R451  100KR2J-1-GP  [R402H16]  127.92 40.89 0 top
R452  -  [0R0402-PAD]  32.04 40.64 0 top
R453  1K5R2J-3-GP  [R402H16]  141.13 40.26 0 top
R454  0R1206-PAD-1-GP  [0R1206-PAD-1]  45.37 37.97 270 top
R455  100KR2J-1-GP  [R402H16]  89.44 37.97 270 top
R456  0R0402-PAD-2-GP  [0R0402-PAD-1]  159.42 31.11 180 bottom
R457  100KR2J-1-GP  [R402H16]  89.44 36.96 90 top
R458  100KR2J-1-GP  [R402H16]  145.7 36.83 270 top
R459  3D3R3F-GP  [R603H22]  153.32 36.58 270 top
R460  3D3R3F-GP  [R603H22]  155.99 36.58 90 top
R461  3D3R3F-GP  [R603H22]  159.42 36.58 270 top
R462  3D3R3F-GP  [R603H22]  162.09 36.58 90 top
R463  47R2J-2-GP  [R402H16]  83.35 35.43 180 top
R464  47R2J-2-GP  [R402H16]  84.49 35.43 180 top
R465  10KR3J-L1-GP  [R603H22]  69.76 34.29 90 top
R466  10KR2J-3-GP  [R402H16]  148.62 39.24 270 top
R467  2K2R2J-2-GP  [R402H16]  135.42 30.86 90 top
R468  100KR2J-1-GP  [R402H16]  138.21 30.61 90 top
R469  240KR3-GP  [R603H22]  69.12 30.48 90 top
R470  4K7R2J-2-GP  [R402H16]  29.17 30.35 180 top
R471  2K2R2J-2-GP  [R402H16]  130.72 30.1 180 top
R472  2K2R2J-2-GP  [R402H16]  131.73 30.1 180 top
R473  2K2R2J-2-GP  [R402H16]  135.42 29.21 90 top
R474  33R2J-2-GP  [R402H16]  29.62 28.83 90 top
R475  -  [0R0402-PAD]  122.97 28.45 270 top
R476  -  [0R0402-PAD]  32.8 28.07 270 top
R477  33R2J-2-GP  [R402H16]  32.8 27.05 270 top
R478  47KR3J-L-GP  [R603H22]  69.76 26.92 0 top
R479  1KR2J-1-GP  [R402H16]  107.09 26.67 0 top
R480  10KR2J-3-GP  [R402H16]  108.11 26.67 180 top
R481  300KR2F-GP  [R402H16]  39.4 26.29 270 top
R482  -  [0R0402-PAD]  83.57 26.29 180 top
R483  1KR2F-3-GP  [R402H16]  32.8 26.04 90 top
R484  10R2F-L-GP  [R402H14]  42.2 25.65 270 top
R485  100KR2F-L1-GP  [R402H16]  117.51 25.53 180 top
R486  -  [0R0402-PAD]  45.5 25.4 180 top
R487  10KR2F-2-GP  [R402H16]  42.2 24.64 90 top
R488  10KR2J-3-GP  [R402H16]  105.06 24.38 0 top
R489  10KR2J-3-GP  [R402H16]  106.08 24.38 0 top
R490  10KR2J-3-GP  [R402H16]  107.09 24.38 0 top
R491  10KR2J-3-GP  [R402H16]  108.11 24.38 0 top
R492  4K7R2J-2-GP  [R402H16]  43.67 24.13 180 top
R493  100KR2J-1-GP  [R402H16]  113.44 23.62 270 top
R494  100R2J-2-GP  [R402H14]  116.24 23.62 270 top
R495  1KR2J-1-GP  [R402H16]  118.14 23.62 270 top
R496  300KR2F-GP  [R402H16]  39.4 23.44 270 top
R498  -  [0R0402-PAD]  39.07 22 0 top
R499  -  [0R0402-PAD]  40.09 22 0 top
R500  100KR2J-1-GP  [R402H16]  42.32 21.59 270 top
R501  10KR2J-3-GP  [R402H16]  44.1 22.61 270 top
R502  0R2J-2-GP  [R402H16]  32.8 21.46 0 top
R503  4K7R2J-2-GP  [R402H16]  37.63 21.46 0 top
R504  0R2J-2-GP  [R402H16]  124.11 20.07 270 top
R505  -  [0R0402-PAD]  37.75 19.56 270 top
R506  10KR2J-3-GP  [R402H16]  126.02 18.16 270 top
R507  100R2J-2-GP  [R402H14]  126.02 17.14 90 top
R508  47R2J-2-GP  [R402H16]  123.48 15.88 90 top
R509  4K7R2J-2-GP  [R402H16]  123.48 14.86 90 top
R510  10KR2J-3-GP  [R402H16]  105.19 14.61 0 top
R511  10KR2J-3-GP  [R402H16]  106.21 14.61 0 top
R512  10KR2J-3-GP  [R402H16]  107.22 14.61 0 top
R513  10KR2J-3-GP  [R402H16]  108.24 14.61 0 top
R514  75R3F-GP  [R603H22]  65.31 12.32 270 top
R515  10KR2J-3-GP  [R402H16]  93.51 12.32 270 top
R516  15KR2F-GP  [R402H16]  93.51 11.3 90 top
R517  10KR2J-3-GP  [R402H16]  41.44 10.41 90 top
R518  1KR2F-3-GP  [R402H16]  38.26 10.34 90 top
R519  2K49R2F-GP  [R402H16]  41.44 9.4 270 top
R520  8K2R2J-3-GP  [R402H16]  47.02 9.4 90 top
R521  1MR3F-GP  [R603H22]  36.74 9.14 270 top
R522  10KR2J-3-GP  [R402H16]  40.67 7.87 0 top
R523  39K2R2F-L-GP  [R402H16]  45.25 7.87 0 top
R524  10KR2J-3-GP  [R402H16]  40.67 5.97 0 top
R525  8K2R2J-3-GP  [R402H16]  33.31 5.59 270 top
R526  15KR2F-GP  [R402H16]  30.77 5.21 0 top
R527  1KR2J-1-GP  [R402H16]  31.78 5.21 180 top
R528  0R0603-PAD-2-GP-U  [0R0603-PAD-1-U]  23.91 224.54 180 bottom
R529  0R0603-PAD-2-GP-U  [0R0603-PAD-1-U]  22.64 224.54 180 bottom
R530  1KR2J-1-GP  [R402H16]  29.62 224.41 180 bottom
R531  -  [0R0402-PAD]  28.61 224.41 0 bottom
R532  1K5R2J-3-GP  [R402H16]  26.45 224.41 0 bottom
R533  -  [0R0805-PAD]  17.69 223.9 0 bottom
R534  10KR2J-3-GP  [R402H16]  124.75 212.6 270 bottom
R535  -  [0R0805-PAD]  8.42 210.82 0 bottom
R536  0R2J-2-GP  [R402H16]  79.28 210.69 0 bottom
R537  8K2R2J-3-GP  [R402H16]  146.85 207.14 90 bottom
R538  39K2R2F-L-GP  [R402H16]  144.94 207.14 90 bottom
R539  10KR2J-3-GP  [R402H16]  122.72 206.38 0 bottom
R540  10KR2J-3-GP  [R402H16]  153.32 205.87 270 bottom
R541  10KR2J-3-GP  [R402H16]  158.15 201.68 180 bottom
R542  -  [0R0805-PAD]  149.26 201.55 180 bottom
R543  24D9R2F-L-GP  [R402H16]  91.85 186.31 0 bottom
R544  2R2J-2-GP  [R402H16]  94.14 184.91 270 bottom
R545  1KR2F-3-GP  [R402H16]  96.55 183.9 180 bottom
R546  1KR2F-3-GP  [R402H16]  96.55 181.99 180 bottom
R547  49D9R2F-GP  [R402H16]  76.87 181.36 180 bottom
R548  49D9R2F-GP  [R402H16]  72.27 181.1 45 bottom
R549  100R2J-2-GP  [R402H14]  83.35 179.71 270 bottom
R550  0R2J-2-GP  [R402H16]  79.54 179.71 270 bottom
R551  0R2J-2-GP  [R402H16]  85.25 179.68 90 bottom
R552  100R2J-2-GP  [R402H14]  86.77 179.32 0 bottom
R553  49D9R2F-GP  [R402H16]  75.93 178.89 270 bottom
R554  51R2J-2-GP  [R402H16]  70.52 178.44 0 bottom
R555  100R2J-2-GP  [R402H14]  85.25 176.53 180 bottom
R556  100R2J-2-GP  [R402H14]  84.23 177.42 180 bottom
R557  240R2F-1-GP  [R402H16]  134.4 171.83 180 bottom
R558  240R2F-1-GP  [R402H16]  133.38 171.83 180 bottom
R559  240R2F-1-GP  [R402H16]  144.94 170.94 180 bottom
R560  240R2F-1-GP  [R402H16]  143.92 170.94 180 bottom
R561  0R2J-2-GP  [R402H16]  85.5 170.69 270 bottom
R562  24D9R2F-L-GP  [R402H16]  85.38 169.29 90 bottom
R563  0R0603-PAD-2-GP-U  [0R0603-PAD-1-U]  94.65 168.28 0 bottom
R564  2K7R2F-GP  [R402H16]  75.29 167.03 90 bottom
R565  100R2F-L1-GP-U  [R402H14]  71.92 164.47 270 bottom
R566  100R2F-L1-GP-U  [R402H14]  71.92 163.45 270 bottom
R567  100R2J-2-GP  [R402H14]  87.41 159.89 180 bottom
R568  100R2J-2-GP  [R402H14]  73.44 159.77 180 bottom
R569  240R2F-1-GP  [R402H16]  154.59 159.64 270 bottom
R570  240R2F-1-GP  [R402H16]  139.35 159.64 270 bottom
R571  -  [0R0402-PAD]  93.89 159.51 180 bottom
R572  100R2J-2-GP  [R402H14]  82.91 159.31 90 bottom
R573  100R2J-2-GP  [R402H14]  76.46 158.88 90 bottom
R574  -  [0R0402-PAD]  71.79 157.35 0 bottom
R575  -  [0R0402-PAD]  73.31 156.97 270 bottom
R576  80D6R2F-L-GP  [R402H16]  96.17 154.94 270 bottom
R577  121R2F-GP  [R402H16]  88.32 154.69 180 bottom
R578  20KR2F-L-GP  [R402H16]  107.6 154.18 90 bottom
R579  10KR2J-3-GP  [R402H16]  170.72 153.92 0 bottom
R580  100R2F-L1-GP-U  [R402H14]  95.16 153.92 270 bottom
R581  0R0603-PAD-2-GP-U  [0R0603-PAD-1-U]  81.77 153.03 270 bottom
R582  0R0603-PAD-2-GP-U  [0R0603-PAD-1-U]  79.81 153.95 0 bottom
R583  0R0603-PAD-2-GP-U  [0R0603-PAD-1-U]  78.65 153.95 0 bottom
R584  0R0603-PAD-2-GP-U  [0R0603-PAD-1-U]  174.4 153.16 90 bottom
R585  4K7R2J-2-GP  [R402H16]  107.6 153.16 270 bottom
R586  -  [0R0402-PAD]  178.47 153.03 180 bottom
R587  49D9R2F-GP  [R402H16]  95.16 152.91 270 bottom
R588  10KR2J-3-GP  [R402H16]  174.28 152.02 90 bottom
R589  0R2J-2-GP  [R402H16]  106.08 151.76 0 bottom
R590  20KR2F-L-GP  [R402H16]  109.13 151.64 180 bottom
R591  100R2F-L1-GP-U  [R402H14]  71.79 151.64 90 bottom
R592  -  [0R0402-PAD]  176.31 151.51 0 bottom
R593  49D9R2F-GP  [R402H16]  95.16 151.51 90 bottom
R594  0R0402-PAD-2-GP  [0R0402-PAD-1]  179.99 150.62 0 bottom
R595  10KR2J-3-GP  [R402H16]  106.46 150.11 90 bottom
R596  1KR2F-3-GP  [R402H16]  155.74 150.37 0 bottom
R597  1KR2F-3-GP  [R402H16]  154.47 150.37 180 bottom
R598  24D9R2F-L-GP  [R402H16]  140.11 149.73 0 bottom
R599  2R2J-2-GP  [R402H16]  137.83 149.73 180 bottom
R600  1KR2F-3-GP  [R402H16]  136.81 149.73 180 bottom
R601  2R2J-2-GP  [R402H16]  151.04 149.48 270 bottom
R602  470R2F-GP  [R402H16]  106.46 149.1 90 bottom
R603  -  [0R0402-PAD]  106.46 148.08 270 bottom
R604  -  [0R0402-PAD]  169.45 147.83 90 bottom
R605  1KR2F-3-GP  [R402H16]  140.11 147.83 180 bottom
R606  24D9R2F-L-GP  [R402H16]  151.04 147.45 90 bottom
R607  100R2F-L1-GP-U  [R402H14]  76.87 146.56 180 bottom
R608  -  [0R0402-PAD]  169.58 144.91 90 bottom
R609  113R2F-GP  [R402H16]  83.98 144.65 180 bottom
R610  200R2F-L-GP  [R402H16]  82.58 144.65 180 bottom
R611  -  [0R0402-PAD]  169.58 143.89 90 bottom
R612  6K2R2F-GP  [R402H16]  178.47 143.15 0 bottom
R613  1KR2J-1-GP  [R402H16]  82.96 143.13 270 bottom
R614  0R3J-0-U-GP  [R603H22]  42.07 141.6 180 bottom
R615  0R0603-PAD-2-GP-U  [0R0603-PAD-1-U]  40.8 141.6 180 bottom
R616  -  [0R0402-PAD]  170.09 141.48 180 bottom
R617  -  [0R0402-PAD]  106.46 140.46 270 bottom
R618  1KR2J-1-GP  [R402H16]  80.81 140.21 0 bottom
R619  -  [0R0402-PAD]  79.79 140.21 0 bottom
R620  1KR2J-1-GP  [R402H16]  78.77 140.21 180 bottom
R621  -  [0R0402-PAD]  169.07 139.95 90 bottom
R622  0R0603-PAD-2-GP-U  [0R0603-PAD-1-U]  83.29 139.57 180 bottom
R623  22R2J-2-GP  [R402H16]  106.46 139.45 90 bottom
R624  -  [0R0402-PAD]  169.07 138.94 90 bottom
R625  0R3J-0-U-GP  [R603H22]  40.8 138.81 180 bottom
R626  8K2R2F-1-GP  [R402H16]  106.46 138.43 270 bottom
R627  -  [0R0402-PAD]  77 138.43 0 bottom
R628  10KR2J-3-GP  [R402H16]  75.98 138.43 180 bottom
R629  1MR2J-1-GP  [R402H16]  109 137.79 180 bottom
R630  0R3J-0-U-GP  [R603H22]  81.39 137.29 0 bottom
R631  -  [0R0402-PAD]  174.02 135 270 bottom
R632  -  [0R0402-PAD]  172.12 135 270 bottom
R633  1KR2J-1-GP  [R402H16]  106.46 135 90 bottom
R634  1KR2J-1-GP  [R402H16]  106.46 133.99 90 bottom
R635  10KR2J-3-GP  [R402H16]  106.71 111.63 0 bottom
R636  -  [0R0402-PAD]  105.95 132.46 180 bottom
R637  -  [0R0402-PAD]  155.35 145.67 180 bottom
R638  -  [0R0402-PAD]  138.34 130.56 270 bottom
R639  -  [0R0402-PAD]  105.95 130.56 0 bottom
R640  0R2J-2-GP  [R402H16]  154.97 130.43 180 bottom
R641  0R2J-2-GP  [R402H16]  139.86 130.05 180 bottom
R642  0R2J-2-GP  [R402H16]  155.58 128.35 0 bottom
R643  -  [0R0402-PAD]  154.57 128.35 0 bottom
R644  20KR2J-L2-GP  [R402H16]  93.51 128.27 0 bottom
R645  10KR2J-3-GP  [R402H16]  92.36 128.27 180 bottom
R646  -  [0R0402-PAD]  106.33 127.13 270 bottom
R647  0R2J-2-GP  [R402H16]  151.93 127.48 270 bottom
R648  -  [0R0402-PAD]  154.97 124.59 0 bottom
R649  0R2J-2-GP  [R402H16]  139.35 126.75 0 bottom
R650  0R2J-2-GP  [R402H16]  131.61 126.62 0 bottom
R651  100KR2J-1-GP  [R402H16]  106.97 125.09 270 bottom
R652  -  [0R0402-PAD]  139 124.76 0 bottom
R653  -  [0R0402-PAD]  133.89 125.73 0 bottom
R654  1KR2J-1-GP  [R402H16]  108.24 122.3 270 bottom
R655  10KR2F-2-GP  [R402H16]  116.24 121.16 180 bottom
R656  1KR2J-1-GP  [R402H16]  115.22 121.16 0 bottom
R657  549R2F-GP  [R402H16]  63.15 118.36 180 bottom
R658  931R2F-1-GP  [R402H16]  62.14 118.36 0 bottom
R659  1K33R2F-GP  [R402H16]  61.12 118.36 0 bottom
R660  40D2R2F-GP  [R402H16]  59.09 118.36 0 bottom
R661  40D2R2F-GP  [R402H16]  58.07 118.36 0 bottom
R662  121R2F-GP  [R402H16]  57.06 118.36 0 bottom
R663  121R2F-GP  [R402H16]  56.04 118.36 0 bottom
R664  10KR3J-L1-GP  [R603H22]  63.66 119.89 270 bottom
R666  10KR3J-L1-GP  [R603H22]  76.61 114.05 90 bottom
R667  0R0603-PAD-2-GP-U  [0R0603-PAD-1-U]  78.01 111.63 180 bottom
R668  0R2J-2-GP  [R402H16]  95.41 116.59 0 bottom
R669  1K33R2F-GP  [R402H16]  47.28 109.73 90 bottom
R670  10KR2J-3-GP  [R402H16]  95.03 109.6 0 bottom
R671  549R2F-GP  [R402H16]  47.79 108.2 0 bottom
R672  0R2J-2-GP  [R402H16]  91.35 108.08 270 bottom
R673  10KR2J-3-GP  [R402H16]  99.98 89.15 90 top
R674  10KR2J-3-GP  [R402H16]  91.73 106.63 0 bottom
R675  10KR2J-3-GP  [R402H16]  41.69 102.62 90 bottom
R676  1KR2F-3-GP  [R402H16]  60.74 100.33 0 bottom
R679  1KR2F-3-GP  [R402H16]  55.79 100.84 270 bottom
R680  60D4R2F-GP  [R402H16]  76.74 97.54 0 bottom
R681  10KR2J-3-GP  [R402H16]  42.45 95.5 180 bottom
R682  -  [0R0402-PAD]  125.76 94.61 180 bottom
R683  0R0402-PAD-2-GP  [0R0402-PAD-1]  96.3 91.69 90 bottom
R684  1KR2F-3-GP  [R402H16]  47.4 91.57 90 bottom
R685  10KR2F-2-GP  [R402H16]  96.3 90.68 270 bottom
R686  40D2R2F  [R402H16]  76.74 90.55 270 bottom
R687  40D2R2F  [R402H16]  73.95 90.42 90 bottom
R688  549R2F-GP  [R402H16]  47.79 90.04 180 bottom
R689  -  [0R0402-PAD]  96.43 89.66 90 bottom
R690  60D4R2F-GP  [R402H16]  77.63 89.53 90 bottom
R691  60D4R2F-GP  [R402H16]  74.46 88.52 270 bottom
R692  100KR2J-1-GP  [R402H16]  94.52 88.65 90 bottom
R693  10KR2J-3-GP  [R402H16]  42.45 86.87 180 bottom
R694  1K33R2F-GP  [R402H16]  47.1 85.04 90 bottom
R695  0R2J-2-GP  [R402H16]  83.73 83.95 0 bottom
R696  0R2J-2-GP  [R402H16]  82.71 83.95 0 bottom
R697  100KR2J-1-GP  [R402H16]  81.57 83.95 180 bottom
R698  931R2F-1-GP  [R402H16]  47.4 83.95 90 bottom
R699  100KR2J-1-GP  [R402H16]  96.68 83.57 180 bottom
R700  100KR2J-1-GP  [R402H16]  95.66 83.57 180 bottom
R701  100KR2J-1-GP  [R402H16]  94.65 83.57 180 bottom
R702  100KR2J-1-GP  [R402H16]  90.58 83.57 0 bottom
R703  100KR2J-1-GP  [R402H16]  89.57 83.57 0 bottom
R704  33KR2J-3-GP  [R402H16]  156.75 81.41 270 bottom
R705  0R0402-PAD-2-GP  [0R0402-PAD-1]  52.61 79.38 270 bottom
R706  10KR2J-3-GP  [R402H16]  57.18 78.87 180 bottom
R707  0R0402-PAD-2-GP  [0R0402-PAD-1]  56.17 78.87 180 bottom
R708  10KR2J-3-GP  [R402H16]  55.15 78.87 0 bottom
R709  10KR2J-3-GP  [R402H16]  54.14 78.87 0 bottom
R710  10KR2J-3-GP  [R402H16]  52.61 78.36 90 bottom
R711  -  [0R0805-PAD]  64.93 75.69 90 bottom
R712  4K7R2J-2-GP  [R402H16]  51.34 75.56 270 bottom
R713  -  [0R0402-PAD]  59.09 74.3 90 bottom
R714  -  [0R0402-PAD]  57.06 73.91 270 bottom
R715  -  [0R0402-PAD]  142.02 72.9 270 bottom
R716  10KR2J-3-GP  [R402H16]  52.81 72.9 90 bottom
R717  20KR2J-L2-GP  [R402H16]  142.02 70.87 90 bottom
R718  10KR2J-3-GP  [R402H16]  60.1 69.47 180 bottom
R719  43K2R2F-L-GP  [R402H16]  70.26 68.96 90 bottom
R720  -  [0R0402-PAD]  54.16 68.68 0 bottom
R721  -  [0R0402-PAD]  53.14 68.68 0 bottom
R722  10KR2F-2-GP  [R402H16]  75.34 69.47 0 bottom
R723  0R2J-2-GP  [R402H16]  74.33 69.47 0 bottom
R724  0R0402-PAD-2-GP  [0R0402-PAD-1]  141.51 68.2 0 bottom
R725  0R2J-2-GP  [R402H16]  135.29 68.45 180 bottom
R726  1KR2J-1-GP  [R402H16]  140.5 68.2 180 bottom
R727  100KR2J-1-GP  [R402H16]  69.38 67.94 90 bottom
R729  10KR2J-3-GP  [R402H16]  62.26 66.17 0 bottom
R730  -  [0R0402-PAD]  58.45 65.91 90 bottom
R731  0R2J-2-GP  [R402H16]  56.55 65.91 270 bottom
R732  10KR2F-2-GP  [R402H16]  138.97 65.28 0 bottom
R733  100KR2F-L1-GP  [R402H16]  131.1 65.28 180 bottom
R734  10KR2F-2-GP  [R402H16]  129.57 65.28 270 bottom
R735  10KR2J-3-GP  [R402H16]  53.63 65.02 90 bottom
R736  10KR2J-3-GP  [R402H16]  56.55 64.9 90 bottom
R737  1KR2J-1-GP  [R402H16]  70.14 62.99 270 bottom
R738  47KR2J-2-GP  [R402H16]  64.55 64.39 90 bottom
R739  100KR2J-1-GP  [R402H16]  72.55 63.88 0 bottom
R740  10KR2J-3-GP  [R402H16]  129.57 64.26 90 bottom
R741  100KR2F-L1-GP  [R402H16]  131.73 63.8 270 bottom
R742  330KR2J-L1-GP  [R402H16]  72.17 62.03 90 bottom
R743  0R2J-2-GP  [R402H16]  26.7 62.99 180 bottom
R744  100KR2J-1-GP  [R402H16]  142.91 63.75 180 bottom
R745  -  [0R0805-PAD]  58.45 62.48 180 bottom
R746  47KR2J-2-GP  [R402H16]  72.17 61.01 90 bottom
R748  0R0603-PAD-2-GP-U  [0R0603-PAD-1-U]  134.78 61.85 270 bottom
R749  -  [0R0402-PAD]  129.45 44.58 180 top
R750  -  [0R0402-PAD]  129.45 61.09 180 bottom
R751  -  [0R0402-PAD]  131.1 44.45 180 top
R752  2D2R3-1-U-GP  [R603H22]  135.54 60.58 90 bottom
R754  -  [0R0402-PAD]  144.81 59.56 270 bottom
R755  47KR2J-2-GP  [R402H16]  56.93 59.18 90 bottom
R756  -  [0R0402-PAD]  143.29 57.66 180 bottom
R758  -  [0R0402-PAD]  144.81 58.42 270 bottom
R759  10KR2J-3-GP  [R402H16]  146.97 58.42 0 bottom
R760  -  [0R0402-PAD]  144.81 57.4 270 bottom
R761  10KR2J-3-GP  [R402H16]  58.58 57.15 90 bottom
R762  10KR2F-2-GP  [R402H16]  125.64 56.64 90 bottom
R763  10KR2J-3-GP  [R402H16]  53.5 56.26 90 bottom
R764  10KR2J-3-GP  [R402H16]  51.6 56.26 90 bottom
R765  4K7R2J-2-GP  [R402H16]  58.58 56.13 90 bottom
